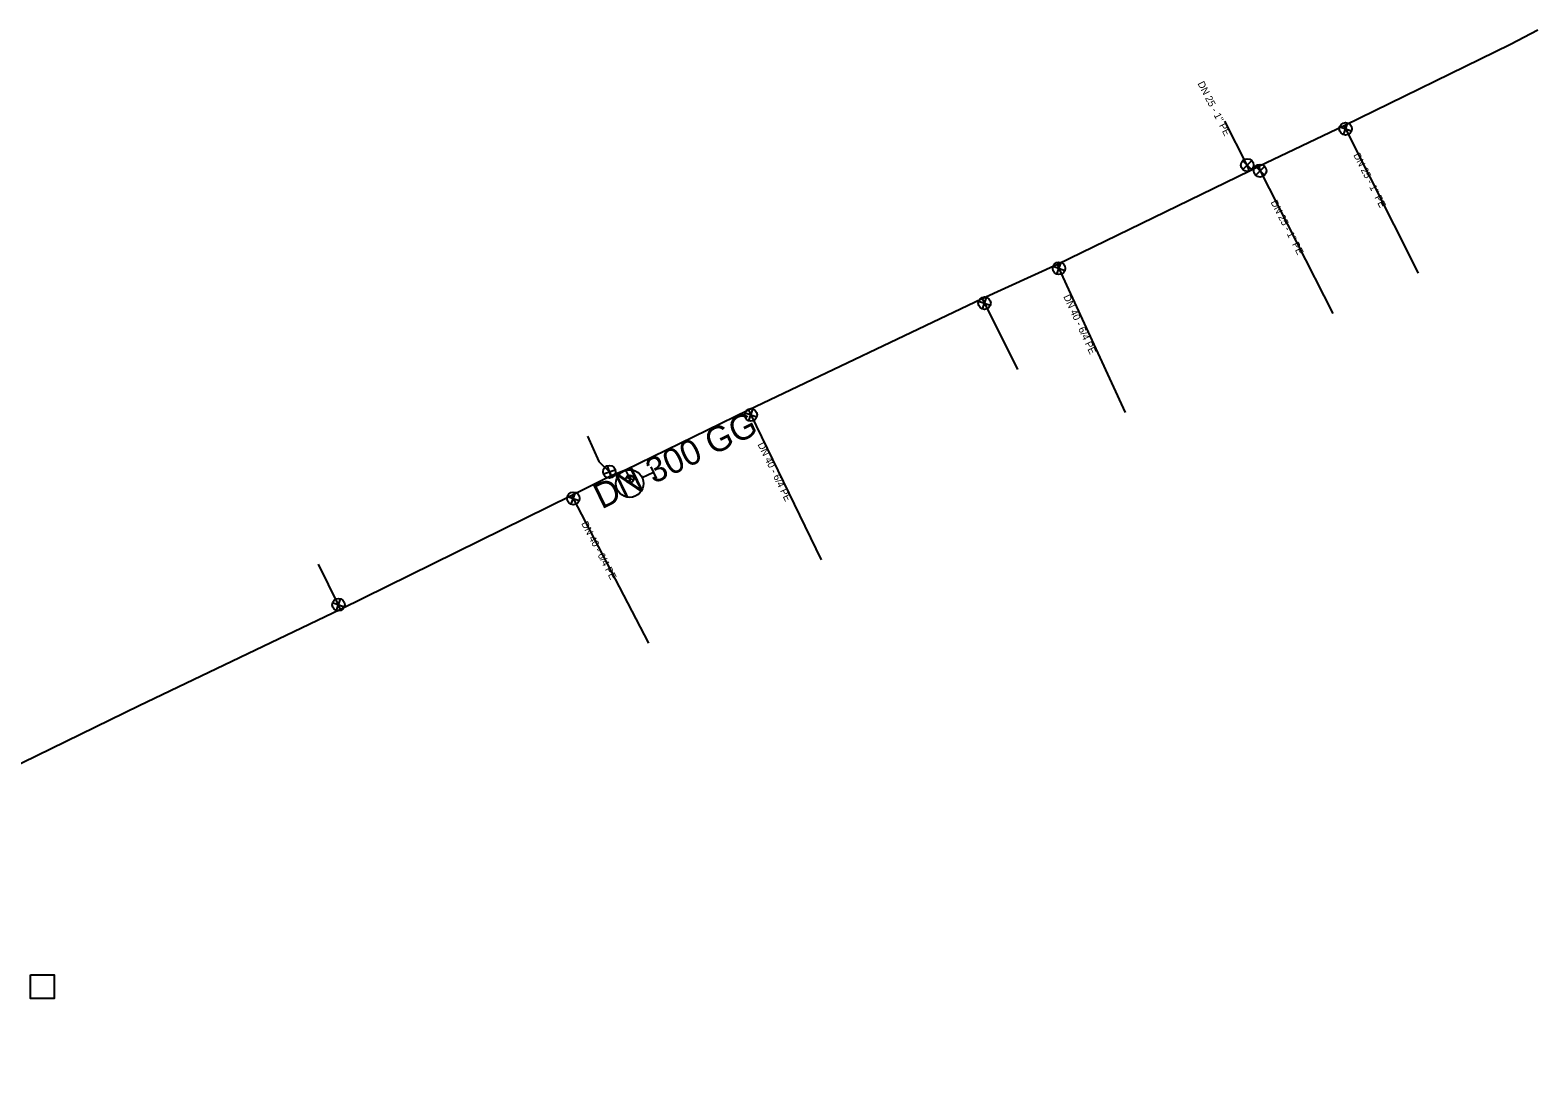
# Model space of a CAD drawing. Extents: x -492390 to -492189, y -1126311 to -1126155.
# Drawn here: x -492285.4 to -492189.3, y -1126288.1 to -1126221.6 of the extents above; entities that cross this region are included whole.
import ezdxf

# ---------------------------------------------------------------- set-up
doc = ezdxf.new("R2010")
doc.units = 0
for name, color, linetype in [('_hydrantova_odbocka_', 7, 'Continuous'), ('_nadz_obvod_sachty_', 7, 'Continuous'), ('_pripojka_prevzato_z_dokumentace_', 7, 'Continuous'), ('_pripojka_priblizne_', 7, 'Continuous'), ('_voda_smvak_prevzato_z_dokumentace_', 7, 'Continuous'), ('Default', 7, 'Continuous'), ('MoLevel 27', 7, 'Continuous'), ('MoLevel 28', 7, 'Continuous'), ('MoLevel 46', 7, 'Continuous'), ('MoLevel 53', 7, 'Continuous'), ('MoLevel 55', 7, 'Continuous')]:
    doc.layers.add(name, color=color, linetype=linetype)

# ---------------------------------------------------------------- blocks, each defined once
blk = doc.blocks.new('_uzaver_')
at = {"layer": 'Default'}
for p, q in [((-0.000035, -0.000035), (0.000035, 0.000035)), ((0.000035, -0.000035), (-0.000035, 0.000035))]:
    blk.add_line(p, q, dxfattribs=at)
for radius in [0.00005, 0.0000025]:
    blk.add_circle((0, 0), radius, dxfattribs=at)
blk = doc.blocks.new('_uzaver_pripojka_')
at = {"layer": 'Default'}
for p, q in [((-0.000035, -0.000035), (0.000035, 0.000035)), ((0.000035, -0.000035), (-0.000035, 0.000035))]:
    blk.add_line(p, q, dxfattribs=at)
for radius in [0.00005, 0.0000025]:
    blk.add_circle((0, 0), radius, dxfattribs=at)
blk = doc.blocks.new('_hydrant_voda_')
at = {"layer": 'Default'}
for p, q in [((-0.0000225, 0.000095), (0.0000225, 0.000095)), ((0, 0.000095), (0, 0.00005))]:
    blk.add_line(p, q, dxfattribs=at)
blk.add_circle((0, 0), 0.00005, dxfattribs=at)

msp = doc.modelspace()

# ---------------------------------------------------------------- linework, layer by layer
at = {"layer": '_hydrantova_odbocka_'}
msp.add_lwpolyline([(-492247.43, -1126249.64), (-492247.15, -1126250.21), (-492247.16, -1126250.5)], dxfattribs=at)
at = {"layer": '_nadz_obvod_sachty_'}
msp.add_lwpolyline([(-492285.35, -1126281.81), (-492283.85, -1126281.811), (-492283.852, -1126283.311), (-492285.352, -1126283.31)], close=True, dxfattribs=at)
at = {"layer": '_pripojka_prevzato_z_dokumentace_'}
for points in [[(-492207.64, -1126230.59), (-492207.79, -1126230.21), (-492209.224, -1126227.413)], [(-492201.62, -1126227.71), (-492201.52, -1126227.9), (-492196.904, -1126237.094)], [(-492207.05, -1126230.3), (-492206.97, -1126230.57), (-492202.323, -1126239.668)], [(-492219.88, -1126236.55), (-492219.79, -1126236.79), (-492215.569, -1126245.973)], [(-492239.58, -1126245.83), (-492239.43, -1126246.13), (-492234.949, -1126255.356)], [(-492249.843, -1126247.49), (-492249.125, -1126249.088), (-492248.45, -1126249.75), (-492248.33, -1126250.02)], [(-492250.84, -1126251.26), (-492250.75, -1126251.45), (-492245.953, -1126260.678)], [(-492265.59, -1126258.52), (-492265.72, -1126258.22), (-492266.99, -1126255.64)]]:
    msp.add_lwpolyline(points, dxfattribs=at)
at = {"layer": '_pripojka_priblizne_'}
msp.add_lwpolyline([(-492224.69, -1126238.73), (-492224.54, -1126239.01), (-492222.43, -1126243.23)], dxfattribs=at)
at = {"layer": '_voda_smvak_prevzato_z_dokumentace_'}
msp.add_lwpolyline([(-492189.265, -1126221.613), (-492191, -1126222.53), (-492201.62, -1126227.71), (-492207.05, -1126230.3), (-492207.64, -1126230.59), (-492219.88, -1126236.55), (-492224.69, -1126238.73), (-492239.58, -1126245.83), (-492247.43, -1126249.64), (-492248.33, -1126250.02), (-492250.84, -1126251.26), (-492265.59, -1126258.52), (-492278.43, -1126264.67), (-492290.57, -1126270.6), (-492291.54, -1126271.24), (-492295.01, -1126273.05), (-492320.201, -1126284.62), (-492327.358, -1126288.114)], dxfattribs=at)

# ---------------------------------------------------------------- block references
at = {"layer": 'MoLevel 27', "xscale": 5000, "yscale": 5000.000000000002, "rotation": 114.481952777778}
msp.add_blockref('_uzaver_', (-492247.15, -1126250.21), dxfattribs=at)
at = {"layer": 'MoLevel 28', "xscale": 17636.684303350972, "yscale": 17636.68430335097, "rotation": -65.588572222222}
msp.add_blockref('_hydrant_voda_', (-492247.16, -1126250.5), dxfattribs=at)
at = {"layer": 'MoLevel 53'}
for p, xscale, yscale, rotation in [((-492201.52, -1126227.9), 7999.999999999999, 8000.000000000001, -64.743733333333), ((-492219.79, -1126236.79), 7999.999999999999, 7999.999999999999, -64.17831111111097), ((-492224.54, -1126239.01), 7999.999999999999, 8000, -64.79511111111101), ((-492239.43, -1126246.13), 8000, 8000, -64.17996666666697), ((-492248.45, -1126249.75), 7999.999999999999, 7999.999999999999, -26.533691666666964), ((-492250.75, -1126251.45), 7999.999999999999, 7999.999999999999, -64.17831111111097), ((-492265.72, -1126258.22), 8000.000000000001, 7999.999999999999, -64.217730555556)]:
    msp.add_blockref('_uzaver_pripojka_', p, dxfattribs=dict(at, xscale=xscale, yscale=yscale, rotation=rotation))
at = {"layer": 'MoLevel 53', "xscale": 7999.999999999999, "yscale": 7999.999999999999}
for p in [(-492207.79, -1126230.21), (-492206.97, -1126230.57)]:
    msp.add_blockref('_uzaver_pripojka_', p, dxfattribs=at)

# ---------------------------------------------------------------- texts
at = {"layer": 'MoLevel 46'}
msp.add_text('DN 300 GG', height=1.6049, rotation=25.88964, dxfattribs=at).set_placement((-492248.946, -1126252.16))
at = {"layer": 'MoLevel 55'}
for s, rotation, p in [("DN 25 - 1'' PE", 297.14386, (-492210.968, -1126225.008)), ("DN 25 - 1'' PE", 296.6597, (-492201.035, -1126229.573)), ("DN 25 - 1'' PE", 297.05666, (-492206.311, -1126232.578)), ('DN 40 - 6/4 PE', 294.68606, (-492219.522, -1126238.587)), ('DN 40 - 6/4 PE', 295.90551, (-492239.015, -1126248.009)), ('DN 40 - 6/4 PE', 297.46681, (-492250.258, -1126253.05))]:
    msp.add_text(s, height=0.455, rotation=rotation, dxfattribs=at).set_placement(p)

doc.saveas('drawing.dxf')
